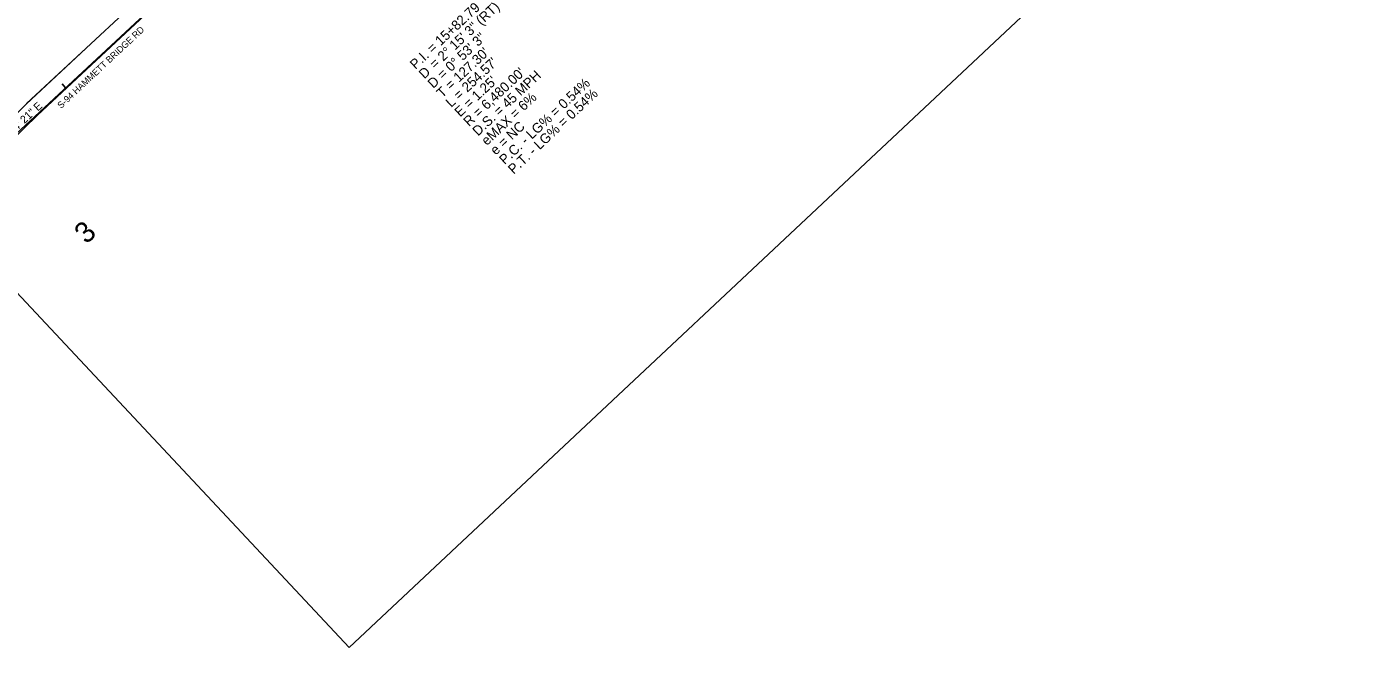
# Model space of a CAD drawing. Extents: x 1623239 to 1625698, y 1118659 to 1120751.
# Drawn here: x 1623812 to 1624829, y 1118693 to 1119168 of the extents above; entities that cross this region are included whole.
import ezdxf

# ---------------------------------------------------------------- set-up
doc = ezdxf.new("R2010")
doc.units = 0
for name, color, linetype in [('RD_EX_DV_TX_Prop', 7, 'Continuous'), ('RD_EX_Road Text', 7, 'Continuous'), ('RD_HC_Cl', 7, 'Continuous'), ('RD_HC_Data', 7, 'Continuous'), ('RD_HC_Data_Tic', 7, 'Continuous'), ('RD_PD_PaintMed', 7, 'Continuous'), ('RD_SHT_ShtClip', 7, 'Continuous')]:
    doc.layers.add(name, color=color, linetype=linetype)

msp = doc.modelspace()

# ---------------------------------------------------------------- linework, layer by layer
at = {"layer": 'RD_HC_Cl'}
msp.add_line((1623608.8, 1118904.3), (1623937.2, 1119209.8), dxfattribs=at)
at = {"layer": 'RD_HC_Data_Tic'}
msp.add_line((1623842.2, 1119121.4), (1623839.5, 1119124.3), dxfattribs=at)
at = {"layer": 'RD_PD_PaintMed'}
for p, q in [((1623812.3, 1119109.3), (1623929.4, 1119218.2)), ((1623820.5, 1119100.5), (1623937.6, 1119209.4)), ((1623812.2, 1119109.2), (1623861.4, 1119155)), ((1623669.2, 1118968.8), (1623812.2, 1119109.2)), ((1623677.6, 1118960.2), (1623820.5, 1119100.5))]:
    msp.add_line(p, q, dxfattribs=at)
at = {"layer": 'RD_SHT_ShtClip'}
for p, q in [((1625372.5, 1119923.9), (1624059.6, 1118692.6)), ((1624059.6, 1118692.6), (1623307.1, 1119494.9))]:
    msp.add_line(p, q, dxfattribs=at)

# ---------------------------------------------------------------- texts
at = {"layer": 'RD_EX_DV_TX_Prop'}
msp.add_text('3', height=16, rotation=43.1627, dxfattribs=at).set_placement((1623858.1, 1119001))
at = {"layer": 'RD_EX_Road Text'}
msp.add_text('S-94 HAMMETT BRIDGE RD', height=5, rotation=43.1627, dxfattribs=at).set_placement((1623838.7, 1119105.1))
at = {"layer": 'RD_HC_Data'}
for s, height, rotation, p in [('P.I. = 15+82.79', 7.5, 43.1627, (1624110.4, 1119135.1)), ('    = 2%%d 15\' 3" (RT)', 7.5, 43.1627, (1624117.2, 1119127.8)), ('D = 0%%d 53\' 3"', 7.5, 43.1627, (1624124, 1119120.5)), ("T = 127.30'", 7.5, 43.1627, (1624130.9, 1119113.2)), ("L = 254.57'", 7.5, 43.1627, (1624137.7, 1119105.9)), ('D', 7.5, 43.1627, (1624117.2, 1119127.8)), ("R = 6,480.00'", 7.5, 43.1627, (1624151.4, 1119091.3)), ('D.S. = 45 MPH', 7.5, 43.1627, (1624158.3, 1119084)), ("E = 1.25'", 7.5, 43.1627, (1624144.6, 1119098.6)), ('P.C. - LG% = 0.54%', 7.5, 43.1627, (1624178.8, 1119062.1)), ('eMAX = 6%', 7.5, 43.1627, (1624165.1, 1119076.7)), ('P.T. - LG% = 0.54%', 7.5, 43.1627, (1624185.6, 1119054.8)), ('N 47%%d 04\' 21" E', 6, 42.9276, (1623785, 1119069.7)), ('e = NC', 7.5, 43.1627, (1624171.9, 1119069.4))]:
    msp.add_text(s, height=height, rotation=rotation, dxfattribs=at).set_placement(p)

doc.saveas('drawing.dxf')
